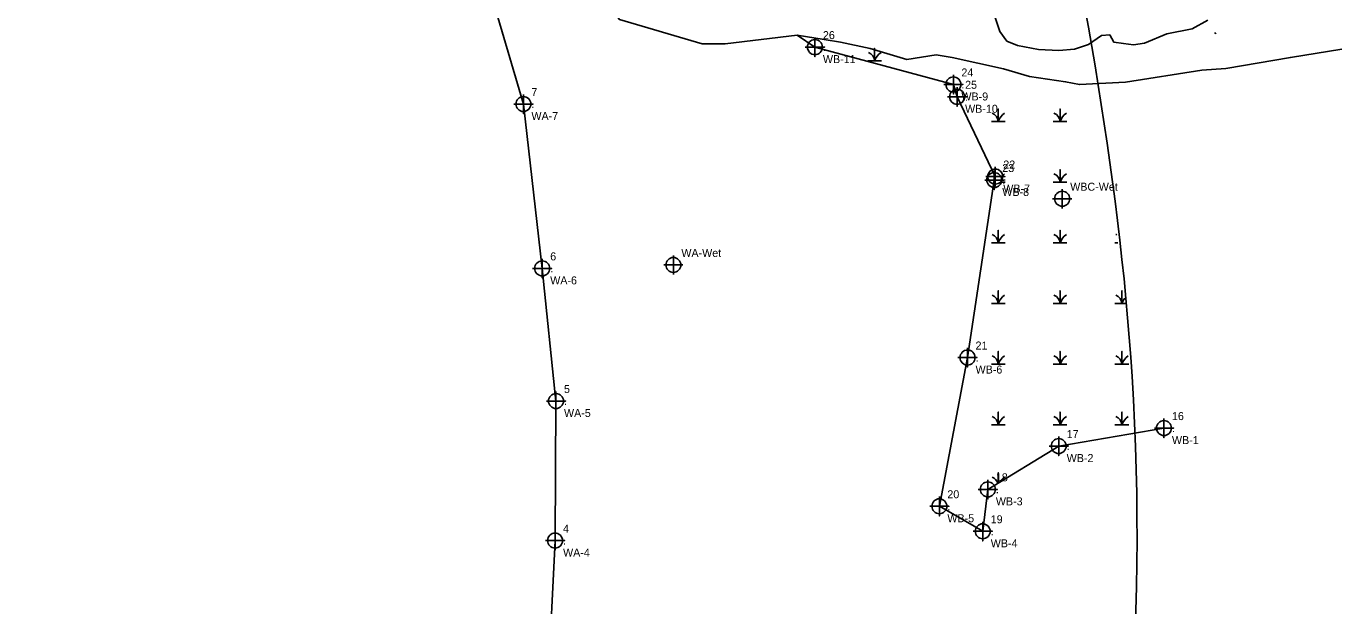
# Model space of a CAD drawing. Extents: x 1835303 to 1835785, y 366400 to 367935.
# Drawn here: x 1835355.5 to 1835766.4, y 366985.6 to 367166.6 of the extents above; entities that cross this region are included whole.
import ezdxf

# ---------------------------------------------------------------- set-up
doc = ezdxf.new("R2010")
doc.units = 0
for name, color, linetype in [('Cogo Default Point CELL', 7, 'Continuous'), ('COGO Default Point Number', 7, 'Continuous'), ('Default', 7, 'Continuous'), ('Exist Environmental Wetland Boundary', 7, 'Continuous'), ('Exist Environmental Wetland Boundary Cogo Comment', 7, 'Continuous'), ('Exist Environmental Wetland Boundary Cogo Elevation', 7, 'Continuous'), ('Exist Environmental Wetland Boundary Cogo Number', 7, 'Continuous'), ('Exist Environmental Wetland Boundary Cogo Point CELL', 7, 'Continuous'), ('Exist Hydro Jurisdictional Stream or Body of Water Mitigable', 7, 'Continuous'), ('Exist Hydro Jurisdictional Stream or Body of Water NEU Mitigable', 7, 'Continuous'), ('Exist Hydro Swamp or Marsh', 7, 'Continuous')]:
    doc.layers.add(name, color=color, linetype=linetype)

msp = doc.modelspace()

# ---------------------------------------------------------------- linework, layer by layer
at = {"layer": 'Cogo Default Point CELL'}
for points in [[(1835679.13, 367115.69), (1835679.13, 367112.69)], [(1835676.13, 367112.69), (1835679.13, 367112.69)], [(1835679.13, 367112.69), (1835682.13, 367112.69)], [(1835679.13, 367112.69), (1835679.13, 367109.69)], [(1835557.64, 367095), (1835557.64, 367092)], [(1835554.64, 367092), (1835557.64, 367092)], [(1835557.64, 367092), (1835560.64, 367092)], [(1835557.64, 367092), (1835557.64, 367089)]]:
    msp.add_lwpolyline(points, dxfattribs=at)
for centre in [(1835679.13, 367112.69), (1835557.64, 367092)]:
    msp.add_circle(centre, 2.34, dxfattribs=at)
at = {"layer": 'Default'}
msp.add_spline([(1835622.69, 367917.35), (1835610.42, 367781.31), (1835628.86, 367442.44), (1835700.95, 367057.13), (1835601.57, 366602.08), (1835470.17, 366400.05)], degree=3, dxfattribs=at)
at = {"layer": 'Exist Environmental Wetland Boundary'}
for points in [[(1835724.65, 367168.46), (1835719.75, 367165.76), (1835711.86, 367164.18), (1835711.86, 367164.18), (1835704.83, 367161.3), (1835701.36, 367160.76), (1835698.3, 367161.19), (1835695.23, 367161.61), (1835693.96, 367163.85), (1835691.43, 367163.71), (1835687.32, 367160.83), (1835682.95, 367159.38), (1835678.09, 367158.98), (1835671.71, 367159.35), (1835665.21, 367160.53), (1835661.84, 367161.89), (1835659.64, 367164.93), (1835658.19, 367169.3)], [(1835710.92, 367041.04), (1835678.03, 367035.43), (1835655.9, 367021.9), (1835654.3, 367008.8), (1835640.75, 367016.62), (1835649.56, 367063.08), (1835657.91, 367118.54), (1835658.22, 367119.62), (1835646.29, 367144.54), (1835645.13, 367148.38), (1835601.87, 367160.05), (1835596.36, 367163.8)]]:
    msp.add_lwpolyline(points, dxfattribs=at)
at = {"layer": 'Exist Environmental Wetland Boundary Cogo Point CELL'}
for points in [[(1835601.87, 367163.05), (1835601.87, 367157.05), (1835601.87, 367160.05), (1835604.87, 367160.05), (1835598.87, 367160.05)], [(1835645.13, 367151.38), (1835645.13, 367145.38), (1835645.13, 367148.38), (1835648.13, 367148.38), (1835642.13, 367148.38)], [(1835510.8, 367145.28), (1835510.8, 367139.28), (1835510.8, 367142.28), (1835513.8, 367142.28), (1835507.8, 367142.28)], [(1835646.29, 367147.54), (1835646.29, 367141.54), (1835646.29, 367144.54), (1835649.29, 367144.54), (1835643.29, 367144.54)], [(1835657.91, 367121.54), (1835657.91, 367115.54), (1835657.91, 367118.54), (1835660.91, 367118.54), (1835654.91, 367118.54)], [(1835658.22, 367122.62), (1835658.22, 367116.62), (1835658.22, 367119.62), (1835661.22, 367119.62), (1835655.22, 367119.62)], [(1835516.67, 367093.93), (1835516.67, 367087.93), (1835516.67, 367090.93), (1835519.67, 367090.93), (1835513.67, 367090.93)], [(1835649.56, 367066.08), (1835649.56, 367060.08), (1835649.56, 367063.08), (1835652.56, 367063.08), (1835646.56, 367063.08)], [(1835520.98, 367052.5), (1835520.98, 367046.5), (1835520.98, 367049.5), (1835523.98, 367049.5), (1835517.98, 367049.5)], [(1835710.92, 367044.04), (1835710.92, 367038.04), (1835710.92, 367041.04), (1835713.92, 367041.04), (1835707.92, 367041.04)], [(1835678.03, 367038.43), (1835678.03, 367032.43), (1835678.03, 367035.43), (1835681.03, 367035.43), (1835675.03, 367035.43)], [(1835655.9, 367024.9), (1835655.9, 367018.9), (1835655.9, 367021.9), (1835658.9, 367021.9), (1835652.9, 367021.9)], [(1835640.75, 367019.62), (1835640.75, 367013.62), (1835640.75, 367016.62), (1835643.75, 367016.62), (1835637.75, 367016.62)], [(1835520.69, 367008.91), (1835520.69, 367002.91), (1835520.69, 367005.91), (1835523.69, 367005.91), (1835517.69, 367005.91)], [(1835654.3, 367011.8), (1835654.3, 367005.8), (1835654.3, 367008.8), (1835657.3, 367008.8), (1835651.3, 367008.8)]]:
    msp.add_lwpolyline(points, dxfattribs=at)
for centre in [(1835601.87, 367160.05), (1835645.13, 367148.38), (1835510.8, 367142.28), (1835646.29, 367144.54), (1835657.91, 367118.54), (1835658.22, 367119.62), (1835516.67, 367090.93), (1835649.56, 367063.08), (1835520.98, 367049.5), (1835710.92, 367041.04), (1835678.03, 367035.43), (1835655.9, 367021.9), (1835640.75, 367016.62), (1835520.69, 367005.91), (1835654.3, 367008.8)]:
    msp.add_circle(centre, 2.34, dxfattribs=at)
at = {"layer": 'Exist Hydro Jurisdictional Stream or Body of Water Mitigable'}
msp.add_lwpolyline([(1835573.83, 367161.12), (1835596.36, 367163.8), (1835604.76, 367162.42), (1835609.89, 367161.59), (1835619.12, 367159.62), (1835630.61, 367156.21), (1835639.79, 367157.65), (1835644.73, 367156.84), (1835660.81, 367153.25), (1835668.89, 367150.89), (1835680.16, 367149.21), (1835684.49, 367148.36), (1835698.91, 367149.06), (1835722.8, 367152.88), (1835730.28, 367153.4), (1835750.41, 367156.81), (1835766.45, 367159.45)], dxfattribs=at)
at = {"layer": 'Exist Hydro Jurisdictional Stream or Body of Water NEU Mitigable'}
for points in [[(1835452.88, 366882.76), (1835503.69, 366919.31), (1835518.49, 366962.01), (1835520.69, 367005.91), (1835520.98, 367049.5), (1835516.67, 367090.93), (1835510.8, 367142.28), (1835496.63, 367190.32), (1835483.12, 367227.97), (1835474.1, 367269.94), (1835464.36, 367306.36), (1835443.97, 367336.69), (1835413.38, 367355.04), (1835384.27, 367375.76), (1835355.5, 367380.19)], [(1835573.83, 367161.12), (1835566.61, 367161.12), (1835540.79, 367168.7), (1835532.97, 367178.64), (1835527.02, 367203.81), (1835518.65, 367239.18), (1835510.27, 367274.56), (1835506.3, 367291.35), (1835478.11, 367335.29), (1835448.35, 367368.55), (1835434.53, 367379.65)]]:
    msp.add_lwpolyline(points, dxfattribs=at)
at = {"layer": 'Exist Hydro Swamp or Marsh'}
for points in [[(1835618.37, 367155.77), (1835620.52, 367155.77), (1835620.52, 367159.72), (1835620.52, 367155.77), (1835622.67, 367155.77)], [(1835656.99, 367136.82), (1835659.14, 367136.82), (1835659.14, 367140.77), (1835659.14, 367136.82), (1835661.29, 367136.82)], [(1835676.3, 367136.82), (1835678.45, 367136.82), (1835678.45, 367140.77), (1835678.45, 367136.82), (1835680.6, 367136.82)], [(1835659.14, 367121.76), (1835659.14, 367121.82), (1835659.14, 367121.76)], [(1835676.3, 367117.87), (1835678.45, 367117.87), (1835678.45, 367121.82), (1835678.45, 367117.87), (1835680.6, 367117.87)], [(1835660.12, 367117.87), (1835661.29, 367117.87)], [(1835656.99, 367098.92), (1835659.14, 367098.92), (1835659.14, 367102.87), (1835659.14, 367098.92), (1835661.29, 367098.92)], [(1835676.3, 367098.92), (1835678.45, 367098.92), (1835678.45, 367102.87), (1835678.45, 367098.92), (1835680.6, 367098.92)], [(1835695.62, 367098.92), (1835696.5, 367098.92)], [(1835656.99, 367079.97), (1835659.14, 367079.97), (1835659.14, 367083.92), (1835659.14, 367079.97), (1835661.29, 367079.97)], [(1835676.3, 367079.97), (1835678.45, 367079.97), (1835678.45, 367083.92), (1835678.45, 367079.97), (1835680.6, 367079.97)], [(1835695.62, 367079.97), (1835697.77, 367079.97), (1835697.77, 367083.92), (1835697.77, 367079.97), (1835698.84, 367079.97)], [(1835656.99, 367061.02), (1835659.14, 367061.02), (1835659.14, 367064.97), (1835659.14, 367061.02), (1835661.29, 367061.02)], [(1835676.3, 367061.02), (1835678.45, 367061.02), (1835678.45, 367064.97), (1835678.45, 367061.02), (1835680.6, 367061.02)], [(1835695.62, 367061.02), (1835697.77, 367061.02), (1835697.77, 367064.97), (1835697.77, 367061.02), (1835699.92, 367061.02)], [(1835656.99, 367042.07), (1835659.14, 367042.07), (1835659.14, 367046.02), (1835659.14, 367042.07), (1835661.29, 367042.07)], [(1835676.3, 367042.07), (1835678.45, 367042.07), (1835678.45, 367046.02), (1835678.45, 367042.07), (1835680.6, 367042.07)], [(1835695.62, 367042.07), (1835697.77, 367042.07), (1835697.77, 367046.02), (1835697.77, 367042.07), (1835699.92, 367042.07)], [(1835659.14, 367023.88), (1835659.14, 367027.07), (1835659.14, 367023.88)]]:
    msp.add_lwpolyline(points, dxfattribs=at)
for centre, radius, start, end in [((1835725.53, 367161.67), 3.07, 56.4988, 67.535), ((1835617.45, 367155.55), 3.07, 4.1403, 67.535), ((1835625.08, 367154.26), 4.81, 122.1274, 161.6222), ((1835656.07, 367136.6), 3.07, 4.1403, 67.535), ((1835663.7, 367135.31), 4.81, 122.1274, 161.6222), ((1835675.39, 367136.6), 3.07, 4.1403, 67.535), ((1835683.01, 367135.31), 4.81, 122.1274, 161.6222), ((1835663.7, 367116.36), 4.81, 122.1274, 131.7097), ((1835675.39, 367117.65), 3.07, 4.1403, 67.535), ((1835683.01, 367116.36), 4.81, 122.1274, 161.6222), ((1835656.07, 367098.7), 3.07, 4.1403, 67.535), ((1835663.7, 367097.41), 4.81, 122.1274, 161.6222), ((1835675.39, 367098.7), 3.07, 4.1403, 67.535), ((1835683.01, 367097.41), 4.81, 122.1274, 161.6222), ((1835694.7, 367098.7), 3.07, 61.6996, 67.535), ((1835656.07, 367079.75), 3.07, 4.1403, 67.535), ((1835663.7, 367078.46), 4.81, 122.1274, 161.6222), ((1835675.39, 367079.75), 3.07, 4.1403, 67.535), ((1835683.01, 367078.46), 4.81, 122.1274, 161.6222), ((1835694.7, 367079.75), 3.07, 4.1403, 67.535), ((1835702.33, 367078.46), 4.81, 139.6107, 161.6222), ((1835656.07, 367060.8), 3.07, 4.1403, 67.535), ((1835663.7, 367059.51), 4.81, 122.1274, 161.6222), ((1835675.39, 367060.8), 3.07, 4.1403, 67.535), ((1835683.01, 367059.51), 4.81, 122.1274, 161.6222), ((1835694.7, 367060.8), 3.07, 4.1403, 67.535), ((1835702.33, 367059.51), 4.81, 122.1274, 161.6222), ((1835656.07, 367041.85), 3.07, 4.1403, 67.535), ((1835663.7, 367040.56), 4.81, 122.1274, 161.6222), ((1835675.39, 367041.85), 3.07, 4.1403, 67.535), ((1835683.01, 367040.56), 4.81, 122.1274, 161.6222), ((1835694.7, 367041.85), 3.07, 4.1403, 67.535), ((1835702.33, 367040.56), 4.81, 122.1274, 161.6222), ((1835656.07, 367022.9), 3.07, 17.09, 67.535), ((1835663.7, 367021.61), 4.81, 122.1274, 147.4337)]:
    msp.add_arc(centre, radius, start, end, dxfattribs=at)

# ---------------------------------------------------------------- texts
at = {"layer": 'COGO Default Point Number'}
for s, p in [('WBC-Wet', (1835681.63, 367115.19)), ('WA-Wet', (1835560.14, 367094.5))]:
    msp.add_text(s, height=2.5, dxfattribs=at).set_placement(p)
at = {"layer": 'Exist Environmental Wetland Boundary Cogo Comment'}
for s, p in [('WB-11', (1835604.37, 367155.05)), ('WB-9', (1835647.63, 367143.38)), ('WA-7', (1835513.3, 367137.28)), ('WB-10', (1835648.79, 367139.54)), ('WB-8', (1835660.41, 367113.54)), ('WB-7', (1835660.72, 367114.62)), ('WA-6', (1835519.17, 367085.93)), ('WB-6', (1835652.06, 367058.08)), ('WA-5', (1835523.48, 367044.5)), ('WB-1', (1835713.42, 367036.04)), ('WB-2', (1835680.53, 367030.43)), ('WB-3', (1835658.4, 367016.9)), ('WB-5', (1835643.25, 367011.62)), ('WB-4', (1835656.8, 367003.8)), ('WA-4', (1835523.19, 367000.91))]:
    msp.add_text(s, height=2.5, dxfattribs=at).set_placement(p)
at = {"layer": 'Exist Environmental Wetland Boundary Cogo Elevation'}
for p in [(1835604.37, 367158.8), (1835647.63, 367147.13), (1835648.79, 367143.29), (1835513.3, 367141.03), (1835660.41, 367117.29), (1835660.72, 367118.37), (1835519.17, 367089.68), (1835652.06, 367061.83), (1835523.48, 367048.25), (1835713.42, 367039.79), (1835680.53, 367034.18), (1835658.4, 367020.65), (1835643.25, 367015.38), (1835656.8, 367007.55), (1835523.19, 367004.66)]:
    msp.add_text('.', height=2.5, dxfattribs=at).set_placement(p)
at = {"layer": 'Exist Environmental Wetland Boundary Cogo Number'}
for s, p in [('26', (1835604.37, 367162.55)), ('24', (1835647.63, 367150.88)), ('25', (1835648.79, 367147.04)), ('7', (1835513.3, 367144.78)), ('23', (1835660.41, 367121.04)), ('22', (1835660.72, 367122.12)), ('6', (1835519.17, 367093.43)), ('21', (1835652.06, 367065.58)), ('5', (1835523.48, 367052)), ('16', (1835713.42, 367043.54)), ('17', (1835680.53, 367037.93)), ('18', (1835658.4, 367024.4)), ('20', (1835643.25, 367019.12)), ('19', (1835656.8, 367011.3)), ('4', (1835523.19, 367008.41))]:
    msp.add_text(s, height=2.5, dxfattribs=at).set_placement(p)

doc.saveas('drawing.dxf')
